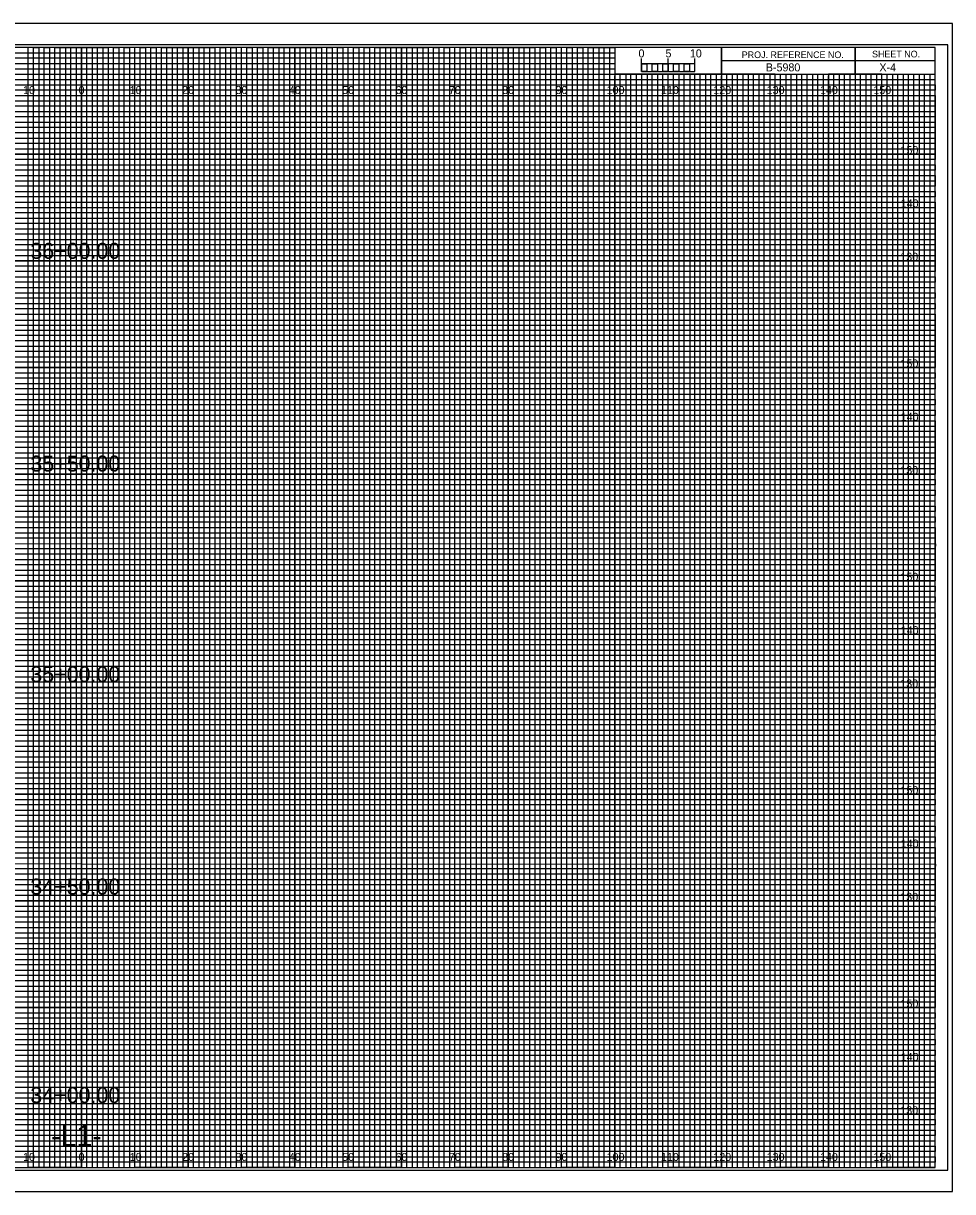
# Model space of a CAD drawing. Extents: x -13 to 323, y -5 to 3294.
# Drawn here: x 149.1 to 323.3, y 655.5 to 874.5 of the extents above; entities that cross this region are included whole.
import ezdxf

# ---------------------------------------------------------------- set-up
doc = ezdxf.new("R2010")
doc.units = 0
for name, color, linetype in [('Prop XS Alignment Label', 7, 'Continuous'), ('Prop XS Bar Scale Labels', 7, 'Continuous'), ('Prop XS Elevation Labels', 7, 'Continuous'), ('Prop XS Offset Labels', 7, 'Continuous'), ('Prop XS Project Number', 7, 'Continuous'), ('Prop XS Sheet Number', 7, 'Continuous'), ('Prop XS Station Labels', 7, 'Continuous'), ('Sheet Cross Section CELL', 7, 'Continuous'), ('Sheet Cross Section Grid Major CELL', 7, 'Continuous'), ('Sheet Cross Section Grid Middle CELL', 7, 'Continuous'), ('Sheet Cross Section Grid Minor 1 CELL', 7, 'Continuous'), ('Sheet Cross Section Grid Minor 2 CELL', 7, 'Continuous'), ('Sheet Cross Section Scale CELL', 7, 'Continuous'), ('Sheet Cutting Line CELL', 7, 'Continuous'), ('Sheet DOT Grid CELL', 7, 'Continuous'), ('Sheet Plot Border Inside CELL', 7, 'Continuous'), ('Sheet Plot Border Outside CELL', 7, 'Continuous')]:
    doc.layers.add(name, color=color, linetype=linetype)

msp = doc.modelspace()

# ---------------------------------------------------------------- linework, layer by layer
at = {"layer": 'Sheet Cross Section CELL'}
for p, q in [((305, 870), (305, 865)), ((305, 865), (305, 870)), ((280, 867.5), (280, 865)), ((320, 867.49), (280, 867.49)), ((280, 865), (320, 865))]:
    msp.add_line(p, q, dxfattribs=at)
for points in [[(320, 870), (0, 870), (0, 660), (320, 660)], [(280, 870), (260, 870), (260, 865.03), (280, 865.03)], [(320, 870), (280, 870), (280, 865), (320, 865)]]:
    msp.add_lwpolyline(points, close=True, dxfattribs=at)
at = {"layer": 'Sheet Cross Section Grid Major CELL'}
for p, q in [((150, 870), (140, 870)), ((150, 660), (150, 870)), ((170, 870), (160, 870)), ((160, 870), (160, 660)), ((170, 660), (170, 870)), ((190, 870), (180, 870)), ((180, 870), (180, 660)), ((190, 660), (190, 870)), ((210, 870), (200, 870)), ((200, 870), (200, 660)), ((210, 660), (210, 870)), ((230, 870), (220, 870)), ((220, 870), (220, 660)), ((230, 660), (230, 870)), ((250, 870), (240, 870)), ((240, 870), (240, 660)), ((250, 660), (250, 870)), ((260, 870), (260, 660)), ((270, 660), (270, 865)), ((290, 865), (280, 865)), ((280, 865), (280, 660)), ((290, 660), (290, 865)), ((310, 865), (300, 865)), ((300, 865), (300, 660)), ((310, 660), (310, 865)), ((160, 660), (150, 660)), ((180, 660), (170, 660)), ((200, 660), (190, 660)), ((220, 660), (210, 660)), ((240, 660), (230, 660)), ((260, 660), (250, 660)), ((280, 660), (270, 660)), ((300, 660), (290, 660)), ((320, 660), (310, 660)), ((320, 660), (320, 660))]:
    msp.add_line(p, q, dxfattribs=at)
for points in [[(0, 860), (320, 860), (320, 850), (0, 850)], [(0, 840), (320, 840), (320, 830), (0, 830)], [(0, 820), (320, 820), (320, 810), (0, 810)], [(0, 800), (320, 800), (320, 790), (0, 790)], [(0, 780), (320, 780), (320, 770), (0, 770)], [(0, 760), (320, 760), (320, 750), (0, 750)], [(0, 740), (320, 740), (320, 730), (0, 730)], [(0, 720), (320, 720), (320, 710), (0, 710)], [(0, 700), (320, 700), (320, 690), (0, 690)], [(0, 680), (320, 680), (320, 670), (0, 670)]]:
    msp.add_lwpolyline(points, dxfattribs=at)
at = {"layer": 'Sheet Cross Section Grid Middle CELL'}
for points in [[(145, 660), (155, 660), (155, 870), (165, 870), (165, 660), (175, 660), (175, 870), (185, 870), (185, 660), (195, 660), (195, 870), (205, 870), (205, 660), (215, 660), (215, 870), (225, 870), (225, 660), (235, 660), (235, 870), (245, 870), (245, 660), (255, 660), (255, 870), (259.93, 870), (260, 870), (260, 865), (264.99, 865), (264.99, 660), (275, 660), (275, 865), (285, 865), (285, 660), (295, 660), (295, 865), (305, 865), (305, 660), (315, 660), (315, 865)], [(0, 865), (275, 865)], [(0, 845), (320, 845), (320, 855), (0, 855)], [(0, 825), (320, 825), (320, 835), (0, 835)], [(0, 805), (320, 805), (320, 815), (0, 815)], [(0, 785), (320, 785), (320, 795), (0, 795)], [(0, 765), (320, 765), (320, 775), (0, 775)], [(0, 745), (320, 745), (320, 755), (0, 755)], [(0, 725), (320, 725), (320, 735), (0, 735)], [(0, 705), (320, 705), (320, 715), (0, 715)], [(0, 685), (320, 685), (320, 695), (0, 695)], [(0, 665), (320, 665), (320, 675), (0, 675)]]:
    msp.add_lwpolyline(points, dxfattribs=at)
at = {"layer": 'Sheet Cross Section Grid Minor 1 CELL'}
for p, q in [((0, 869), (260, 869)), ((260, 867.98), (0, 867.98)), ((260, 869), (260, 867.98)), ((0, 867), (260, 867)), ((260, 865.89), (0, 865.89)), ((260, 867), (260, 865.89)), ((0, 864), (320, 864))]:
    msp.add_line(p, q, dxfattribs=at)
for points in [[(0, 863), (270, 863), (320, 863), (320, 862), (0, 862)], [(0, 861), (320, 861), (320, 859), (0, 859)], [(0, 858), (320, 858), (320, 857), (0, 856.98)], [(0, 856), (320, 856), (320, 854), (0, 854)], [(0, 853), (320, 853), (320, 852), (0, 852)], [(0, 851), (320, 851), (320, 849), (0, 849)], [(0, 848), (320, 848), (320, 847), (0, 847)], [(0, 846), (320, 846), (320, 844), (0, 844)], [(0, 843), (320, 843), (320, 842), (0, 842)], [(0, 841), (320, 841), (320, 839), (0, 839)], [(0, 838), (320, 838), (320, 837), (0, 837)], [(0, 836), (320, 836), (320, 833.95), (320, 833), (320, 832), (0, 832)], [(0, 834), (320, 834), (320, 833), (0, 833)], [(0, 831), (320, 831), (320, 829), (0, 829.03)], [(0, 829.03), (320, 829), (320, 828), (0, 828)], [(0, 827), (320, 827), (320, 826), (0, 826)], [(0, 824), (320, 824), (320, 823), (0, 823)], [(0, 822), (320, 822), (320, 821), (0, 821)], [(-0.07, 818.89), (320, 818.89), (320, 817.88), (-0.07, 817.88)], [(0, 817), (320, 817), (320, 816), (0, 816)], [(0, 814), (320, 814), (320, 813), (0, 813)], [(0, 812), (320, 812), (320, 811), (0, 811)], [(0, 809), (320, 809), (320, 808), (0, 808)], [(0, 807), (320, 807), (320, 806), (0, 806)], [(0, 804), (320, 804), (320, 803), (0, 803)], [(0, 802), (320, 802), (320, 801), (0, 801)], [(0, 799), (320, 799), (319.99, 797.98), (0, 798)], [(0, 797), (320, 797), (320, 796), (0, 796)], [(0, 794), (320, 794), (320, 793), (0, 793)], [(0, 792), (320, 792), (320, 791), (0, 791)], [(0, 789), (320, 789), (320, 788), (0, 788)], [(0, 787), (320, 787), (320, 786), (0, 786)], [(0, 784), (320, 784), (320, 783), (0, 783)], [(0, 782), (320, 782), (320, 781), (0, 781)], [(0, 779), (320, 779), (320, 778), (0, 778)], [(0, 776.99), (320.07, 776.91), (320, 776), (0, 776)], [(0, 774), (320, 774), (320, 773), (0, 773)], [(0, 772), (320, 772), (320, 771), (0, 771)], [(0, 769), (320, 769), (320, 768), (0, 768)], [(0, 767), (320, 767), (320, 766), (0, 766)], [(0, 764), (320, 764), (320, 763), (0, 763)], [(0, 762), (320, 762), (320, 761), (0, 761)], [(0, 759), (320, 759), (320, 758), (0, 758)], [(0, 757), (320, 757), (320, 756), (0, 756)], [(0, 754), (320, 754), (320, 753), (0, 753)], [(0, 752), (320, 752), (320, 751), (0, 751)], [(0, 749), (320, 749), (320, 748), (0, 748)], [(0, 747), (320, 747), (320, 746), (0, 746)], [(0, 744), (320, 744), (320, 743), (0, 743)], [(0, 742), (320, 742), (320, 741), (0, 741)], [(0, 739), (320, 739), (319.99, 737.98), (0, 738)], [(0, 737), (320, 737), (320, 736), (0, 736)], [(0, 734), (320, 734), (320, 733), (0, 733)], [(0, 732), (320, 732), (320, 731), (0, 731)], [(0, 729), (320, 729), (320, 728), (0, 728)], [(0, 727), (320, 727), (320, 726), (0, 726)], [(0, 724), (320, 724), (320, 723), (0, 723)], [(0, 722), (320, 722), (320, 721), (0, 721)], [(0, 719), (320, 719), (320, 718), (0, 718)], [(0, 716.99), (320.07, 716.91), (320, 716), (0, 716)], [(0, 714), (320, 714), (320, 713), (0, 713)], [(0, 712), (320, 712), (320, 711), (0, 711)], [(0, 709), (320, 709), (320, 708), (0, 708)], [(0, 707), (320, 707), (320, 706), (0, 706)], [(0, 704), (320, 704), (320, 703), (0, 703)], [(0, 702), (320, 702), (320, 701), (0, 701)], [(0, 699), (320, 699), (320, 698), (0, 698)], [(0, 697), (320, 697), (320, 696), (0, 696)], [(0, 694), (320, 694), (320, 693), (0, 693)], [(0, 692), (320, 692), (320, 691), (0, 691)], [(0, 689), (320, 689), (320, 688), (0, 688)], [(0, 687), (320, 687), (320, 686), (0, 686)], [(0, 684), (320, 684), (320, 683), (0, 683)], [(0, 682), (320, 682), (320, 681), (0, 681)], [(0, 679), (320, 679), (320, 678), (0, 678)], [(0, 677), (320, 677), (320, 676), (0, 676)], [(0, 674), (320, 674), (320, 673), (0, 673)], [(0, 672), (320, 672), (320, 671), (0, 671)], [(0, 669), (320, 669), (320, 668), (0, 668)], [(0, 667), (320, 667), (320, 666), (0, 666)], [(0, 664), (320, 664), (320, 663), (0, 663)], [(0, 662), (320, 662), (320, 661), (0, 661)]]:
    msp.add_lwpolyline(points, dxfattribs=at)
at = {"layer": 'Sheet Cross Section Grid Minor 2 CELL'}
for p, q in [((267, 865), (266.01, 865)), ((266.01, 865), (266.01, 660)), ((267, 660), (267, 865)), ((269, 865), (268, 865)), ((268, 865), (268, 660)), ((269, 660), (269, 865)), ((266.01, 660), (265, 660)), ((268, 660), (267, 660))]:
    msp.add_line(p, q, dxfattribs=at)
for points in [[(150, 660), (151, 660), (151, 870), (152, 870), (152, 660)], [(152, 660), (153, 660), (153, 870), (154, 870), (154, 660)], [(155, 660), (156, 660), (156, 870), (157, 870), (157, 660)], [(157, 660), (158, 660), (158, 870), (159, 870), (159, 660)], [(160, 660), (161, 660), (161, 870), (162, 870), (162, 660)], [(162, 660), (163, 660), (163, 870), (164, 870), (164, 660)], [(165, 660), (166, 660), (166, 870), (167, 870), (167, 660)], [(167, 660), (168, 660), (168, 870), (169, 870), (169, 660)], [(170, 660), (171, 660), (171, 870), (172, 870), (172, 660)], [(172, 660), (173, 660), (173, 870), (174, 870), (174, 660)], [(175, 660), (176, 660), (176, 870), (177, 870), (177, 660)], [(177, 660), (178, 660), (178, 870), (179, 870), (179, 660)], [(180, 660), (181, 660), (181, 870), (182, 870), (182, 660)], [(182, 660), (183, 660), (183, 870), (184, 870), (184, 660)], [(185, 660), (186, 660), (186, 870), (187, 870), (187, 660)], [(187, 660), (188, 660), (188, 870), (189, 870), (189, 660)], [(190, 660), (191, 660), (191, 870), (192, 870), (192, 660)], [(192, 660), (193, 660), (193, 870), (194, 870), (194, 660)], [(195, 660), (196, 660), (196, 870), (197, 870), (197, 660)], [(197, 660), (198, 660), (198, 870), (199, 870), (199, 660)], [(200, 660), (201, 660), (201, 870), (202, 870), (202, 660)], [(202, 660), (203, 660), (203, 870), (204, 870), (204, 660)], [(205, 660), (206, 660), (206, 870), (207, 870), (207, 660)], [(207, 660), (208, 660), (208, 870), (209, 870), (209, 660)], [(210, 660), (211, 660), (211, 870), (212, 870), (212, 660)], [(212, 660), (213, 660), (213, 870), (214, 870), (214, 660)], [(215, 660), (216, 660), (216, 870), (217, 870), (217, 660)], [(217, 660), (218, 660), (218, 870), (219, 870), (219, 660)], [(220, 660), (221, 660), (221, 870), (222, 870), (222, 660)], [(222, 660), (223, 660), (223, 870), (224, 870), (224, 660)], [(225, 660), (226, 660), (226, 870), (227, 870), (227, 660)], [(227, 660), (228, 660), (228, 870), (229, 870), (229, 660)], [(230, 660), (231, 660), (231, 870), (232, 870), (232, 660)], [(232, 660), (233, 660), (233, 870), (234, 870), (234, 660)], [(235, 660), (236, 660), (236, 870), (237, 870), (237, 660)], [(237, 660), (238, 660), (238, 870), (239, 870), (239, 660)], [(240, 660), (241, 660), (241, 870), (242, 870), (242, 660)], [(242, 660), (243, 660), (243, 870), (244, 870), (244, 660)], [(245, 660), (246, 660), (246, 870), (247, 870), (247, 660)], [(247, 660), (248, 660), (248, 870), (249, 870), (249, 660)], [(250, 660), (251, 660), (251, 870), (252, 870), (252, 660)], [(252, 660), (253, 660), (253, 870), (254, 870), (254, 660)], [(255, 660), (256, 660), (256, 870), (257, 870), (257, 660)], [(257, 660), (258, 660), (258, 870), (259, 870), (259, 660)], [(260, 660), (261, 660), (261, 865), (262.02, 865), (262.02, 660)], [(262, 660), (263, 660), (263, 865), (263.99, 865), (263.99, 660)], [(270, 660), (270.98, 660), (270.98, 865), (272, 865), (272, 660)], [(272, 660), (273, 660), (273, 865), (274.05, 865), (274.05, 660)], [(275, 660), (276, 660), (276, 865), (277, 865), (277, 660)], [(277, 660), (278, 660), (278, 865), (279, 865), (279, 660)], [(280, 660), (281, 660), (281, 865), (282, 865), (282, 660)], [(282, 660), (283, 660), (283, 865), (284, 865), (284, 660)], [(285, 660), (286, 660), (286, 865), (287, 865), (287, 660)], [(287, 660), (288, 660), (288, 865), (289, 865), (289, 660)], [(290, 660), (291, 660), (291, 865), (292, 865), (292, 660)], [(292, 660), (293, 660), (293, 865), (294, 865), (294, 660)], [(295, 660), (296, 660), (296, 865), (297, 865), (297, 660)], [(297, 660), (298, 660), (298, 865), (299, 865), (299, 660)], [(300, 660), (301, 660), (301, 865), (302, 865), (302, 660)], [(302, 660), (303, 660), (303, 865), (304, 865), (304, 660)], [(305, 660), (306, 660), (306, 865), (307, 865), (307, 660)], [(307, 660), (308, 660), (308, 865), (309, 865), (309, 660)], [(310, 660), (311, 660), (311, 865), (312, 865), (312, 660)], [(312, 660), (313, 660), (313, 865), (314, 865), (314, 660)], [(315, 660), (316, 660), (316, 865), (317, 865), (317, 660)], [(317, 660), (318, 660), (318, 865), (319, 865), (319, 660)]]:
    msp.add_lwpolyline(points, dxfattribs=at)
at = {"layer": 'Sheet Cross Section Scale CELL'}
for p, q in [((265, 865.49), (265, 867.9)), ((265, 866.9), (265, 867.9)), ((270, 865.49), (270, 867.9)), ((275, 865.49), (275, 867.9)), ((275, 866.9), (275, 867.9))]:
    msp.add_line(p, q, dxfattribs=at)
for points in [[(275, 866.9), (265, 866.9), (265, 865.49), (275, 865.49)], [(265, 866.9), (266, 866.9), (266, 865.49), (265, 865.49)], [(267, 866.9), (268, 866.9), (268, 865.49), (267, 865.49)], [(269, 866.9), (270, 866.9), (270, 865.49), (269, 865.49)], [(271, 866.9), (272, 866.9), (272, 865.49), (271, 865.49)], [(273, 866.9), (274, 866.9), (274, 865.49), (273, 865.49)]]:
    msp.add_lwpolyline(points, close=True, dxfattribs=at)
at = {"layer": 'Sheet Cutting Line CELL'}
for p, q in [((323.3, 874.5), (-13.4, 874.5)), ((-13.4, 655.5), (323.3, 655.5))]:
    msp.add_line(p, q, dxfattribs=at)
at = {"layer": 'Sheet DOT Grid CELL'}
for p, q in [((150, 660), (150, 870)), ((160, 660), (160, 870)), ((170, 660), (170, 870)), ((180, 660), (180, 870)), ((190, 660), (190, 870)), ((200, 660), (200, 870)), ((210, 660), (210, 870)), ((220, 660), (220, 870)), ((230, 660), (230, 870)), ((240, 660), (240, 870)), ((250, 660), (250, 870)), ((260, 660), (260, 864.69)), ((270, 660), (270, 864.69)), ((280, 660), (280, 864.69)), ((290, 660), (290, 864.69)), ((300, 660), (300, 864.69)), ((310, 660), (310, 864.69)), ((0, 860), (320, 860)), ((0, 850), (320, 850)), ((0, 840), (320, 840)), ((0, 830), (320, 830)), ((0, 820), (320, 820)), ((0, 810), (320, 810)), ((0, 800), (320, 800)), ((0, 790), (320, 790)), ((0, 780), (320, 780)), ((0, 770), (320, 770)), ((0, 760), (320, 760)), ((0, 750), (320, 750)), ((0, 740), (320, 740)), ((0, 730), (320, 730)), ((0, 720), (320, 720)), ((0, 710), (320, 710)), ((0, 700), (320, 700)), ((0, 690), (320, 690)), ((0, 680), (320, 680)), ((0, 670), (320, 670))]:
    msp.add_line(p, q, dxfattribs=at)
at = {"layer": 'Sheet Plot Border Inside CELL'}
msp.add_lwpolyline([(-10.8, 659.5), (322.4, 659.5), (322.4, 870.5), (-10.8, 870.5)], close=True, dxfattribs=at)
at = {"layer": 'Sheet Plot Border Outside CELL'}
msp.add_lwpolyline([(-13.4, 655.5), (323.3, 655.5), (323.3, 874.5), (-13.4, 874.5)], close=True, dxfattribs=at)

# ---------------------------------------------------------------- texts
at = {"layer": 'Prop XS Alignment Label'}
msp.add_text('-L1-', height=4, dxfattribs=at).set_placement((154.28, 664))
at = {"layer": 'Prop XS Bar Scale Labels'}
for s, p in [('5', (269.47, 868.12)), ('10', (274.04, 868.12))]:
    msp.add_text(s, height=1.5, dxfattribs=at).set_placement(p)
at = {"layer": 'Prop XS Elevation Labels'}
for s, p in [('150', (313.52, 850)), ('140', (313.57, 840)), ('130', (313.49, 830)), ('150', (313.52, 810)), ('140', (313.57, 800)), ('130', (313.49, 790)), ('150', (313.52, 770)), ('140', (313.57, 760)), ('130', (313.49, 750)), ('150', (313.52, 730)), ('140', (313.57, 720)), ('130', (313.49, 710)), ('150', (313.52, 690)), ('140', (313.57, 680)), ('130', (313.49, 670))]:
    msp.add_text(s, height=1.5, dxfattribs=at).set_placement(p)
at = {"layer": 'Prop XS Offset Labels'}
for s, p in [('10', (149.04, 861.25)), ('0', (159.45, 861.25)), ('0', (159.45, 861.25)), ('10', (169.04, 861.25)), ('20', (178.86, 861.25)), ('30', (188.86, 861.25)), ('40', (198.86, 861.25)), ('50', (208.86, 861.25)), ('60', (218.86, 861.25)), ('70', (228.86, 861.25)), ('80', (238.86, 861.25)), ('90', (248.86, 861.25)), ('100', (258.44, 861.25)), ('110', (268.62, 861.25)), ('120', (278.44, 861.25)), ('130', (288.44, 861.25)), ('140', (298.44, 861.25)), ('150', (308.44, 861.25)), ('10', (149.04, 661.25)), ('0', (159.45, 661.25)), ('0', (159.45, 661.25)), ('10', (169.04, 661.25)), ('20', (178.86, 661.25)), ('30', (188.86, 661.25)), ('40', (198.86, 661.25)), ('50', (208.86, 661.25)), ('60', (218.86, 661.25)), ('70', (228.86, 661.25)), ('80', (238.86, 661.25)), ('90', (248.86, 661.25)), ('100', (258.44, 661.25)), ('110', (268.62, 661.25)), ('120', (278.44, 661.25)), ('130', (288.44, 661.25)), ('140', (298.44, 661.25)), ('150', (308.44, 661.25))]:
    msp.add_text(s, height=1.5, dxfattribs=at).set_placement(p)
at = {"layer": 'Prop XS Project Number'}
msp.add_text('B-5980', height=1.5, dxfattribs=at).set_placement((288.28, 865.5))
at = {"layer": 'Prop XS Sheet Number'}
msp.add_text('X-4', height=1.5, dxfattribs=at).set_placement((309.57, 865.5))
at = {"layer": 'Prop XS Station Labels'}
for s, p in [('36+00.00', (150.41, 830.36)), ('35+50.00', (150.41, 790.48)), ('35+00.00', (150.41, 750.99)), ('34+50.00', (150.41, 711.18)), ('34+00.00', (150.41, 672.11))]:
    msp.add_text(s, height=3, dxfattribs=at).set_placement(p)
at = {"layer": 'Sheet Cross Section CELL'}
for s, p in [('PROJ. REFERENCE NO.', (283.77, 867.99)), ('SHEET NO.', (308.19, 868.12))]:
    msp.add_text(s, height=1.25, dxfattribs=at).set_placement(p)
at = {"layer": 'Sheet Cross Section Scale CELL'}
msp.add_text('0', height=1.5, dxfattribs=at).set_placement((264.41, 868.12))

doc.saveas('drawing.dxf')
